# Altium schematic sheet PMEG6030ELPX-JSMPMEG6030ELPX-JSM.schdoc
size 127 x 101 mm
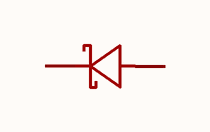
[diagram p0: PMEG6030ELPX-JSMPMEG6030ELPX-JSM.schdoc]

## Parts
D?  pmeg6030elpx-jsm  [SMAF_L3.5-W2.6-LS4.7-RD]  (value not drawn)

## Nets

Not connected (* = marked no-connect by the designer): D? 1(K) 2(A)

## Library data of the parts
D? = pmeg6030elpx-jsm: 二极管配置:1个独立式;正向压降(Vf):700mV@3A;直流反向耐压(Vr):60V;整流电流:3A;; Manufacturer: JSMSEMI(杰盛微); AddInBom: yes; ModelId: 4caf566195a049cf809ac17c4d641932; ModelName: SMAF_L3.5-W2.6-LS4.7-RD-1; ModelTransform: 183.0705,102.362,0,0,0,0,0,0,0; Diode Configuration: 1个独立式; Voltage - DC Reverse(Vr): 60V; Current - Rectified: 3A; Reverse Leakage Current (Ir): 550uA; Operating Junction Temperature Range: -55℃~+150℃; Non-Repetitive Peak Forward Surge Current: 80A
